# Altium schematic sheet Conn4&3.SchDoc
size A
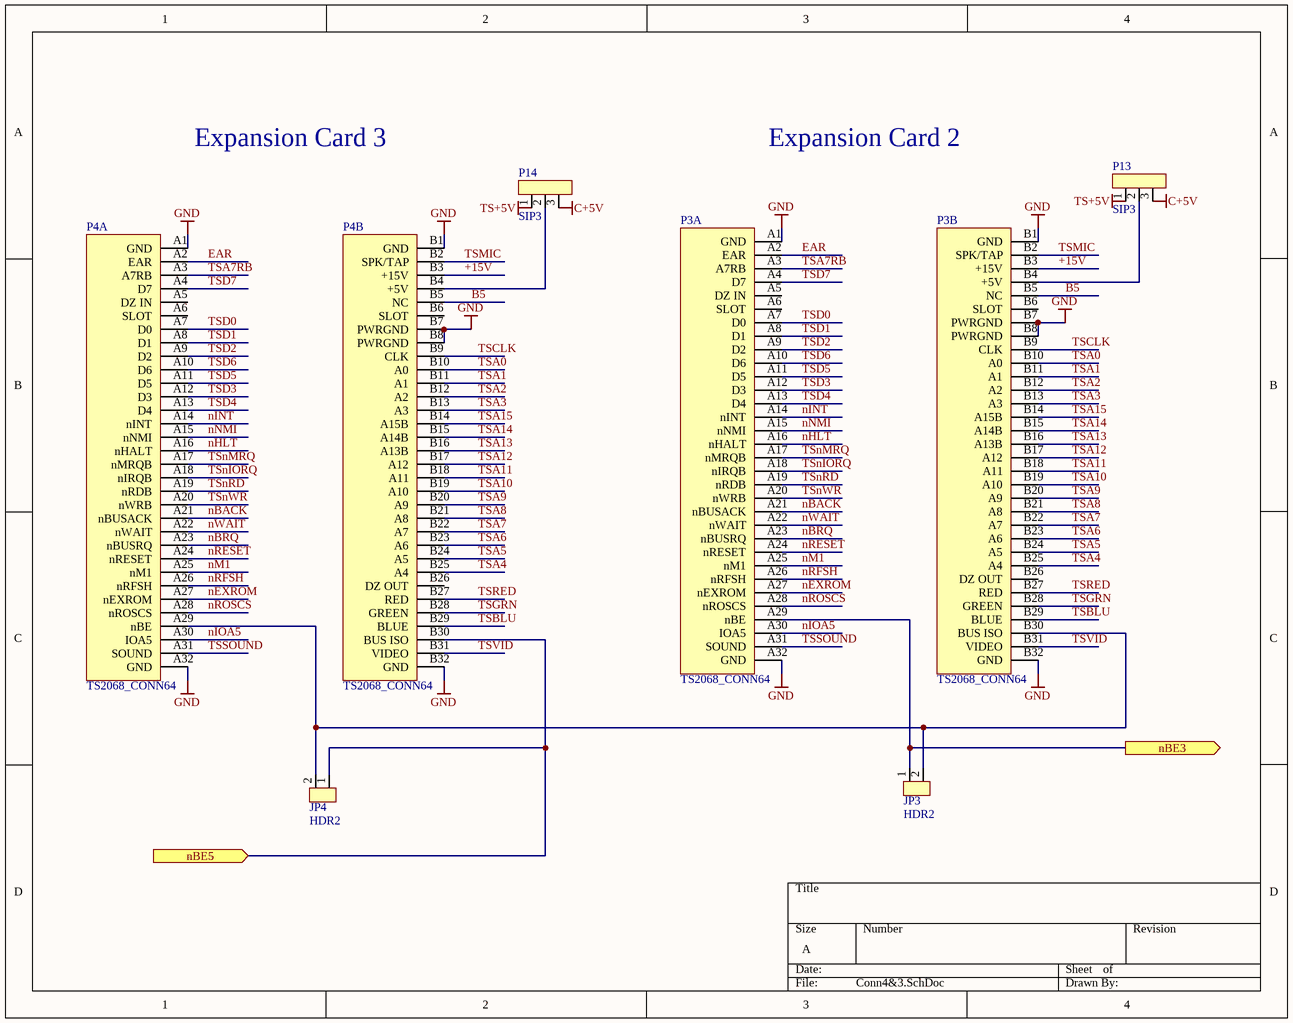
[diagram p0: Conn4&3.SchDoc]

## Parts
JP3  HDR2  [HDR2]
JP4  HDR2  [HDR2]
P3  TS2068_CONN64  [64CARDEDGE]  (parts A,B of 2)
P4  TS2068_CONN64  [64CARDEDGE]  (parts A,B of 2)
P13  SIP3  [SIP3]
P14  SIP3  [SIP3]

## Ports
nBE3 (out), nBE5 (in)

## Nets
C+5V: P13.3 P14.3
GND: P3.A1(GND) P3.A32(GND) P3.B1(GND) P3.B7(PWRGND) P3.B8(PWRGND) P3.B32(GND) P4.A1(GND) P4.A32(GND) P4.B1(GND) P4.B7(PWRGND) P4.B8(PWRGND) P4.B32(GND)
TS+5V: P13.1 P14.1
+15V: P3.B3(+15V) P4.B3(+15V)
B5: P3.B5(NC) P4.B5(NC)
EAR: P3.A2(EAR) P4.A2(EAR)
nBACK: P3.A21(nBUSACK) P4.A21(nBUSACK)
nBE3: JP3.1 P3.A29(nBE) ; port nBE3
nBE5: JP4.1 P4.B30(BUS_ISO) ; port nBE5
nBRQ: P3.A23(nBUSRQ) P4.A23(nBUSRQ)
nEXROM: P3.A27(nEXROM) P4.A27(nEXROM)
nHLT: P3.A16(nHALT) P4.A16(nHALT)
nINT: P3.A14(nINT) P4.A14(nINT)
nIOA5: P3.A30(IOA5) P4.A30(IOA5)
nM1: P3.A25(nM1) P4.A25(nM1)
nNMI: P3.A15(nNMI) P4.A15(nNMI)
nRESET: P3.A24(nRESET) P4.A24(nRESET)
nRFSH: P3.A26(nRFSH) P4.A26(nRFSH)
nROSCS: P3.A28(nROSCS) P4.A28(nROSCS)
nWAIT: P3.A22(nWAIT) P4.A22(nWAIT)
TSA0: P3.B10(A0) P4.B10(A0)
TSA1: P3.B11(A1) P4.B11(A1)
TSA2: P3.B12(A2) P4.B12(A2)
TSA3: P3.B13(A3) P4.B13(A3)
TSA4: P3.B25(A4) P4.B25(A4)
TSA5: P3.B24(A5) P4.B24(A5)
TSA6: P3.B23(A6) P4.B23(A6)
TSA7: P3.B22(A7) P4.B22(A7)
TSA7RB: P3.A3(A7RB) P4.A3(A7RB)
TSA8: P3.B21(A8) P4.B21(A8)
TSA9: P3.B20(A9) P4.B20(A9)
TSA10: P3.B19(A10) P4.B19(A10)
TSA11: P3.B18(A11) P4.B18(A11)
TSA12: P3.B17(A12) P4.B17(A12)
TSA13: P3.B16(A13B) P4.B16(A13B)
TSA14: P3.B15(A14B) P4.B15(A14B)
TSA15: P3.B14(A15B) P4.B14(A15B)
TSBLU: P3.B29(BLUE) P4.B29(BLUE)
TSCLK: P3.B9(CLK) P4.B9(CLK)
TSD0: P3.A7(D0) P4.A7(D0)
TSD1: P3.A8(D1) P4.A8(D1)
TSD2: P3.A9(D2) P4.A9(D2)
TSD3: P3.A12(D3) P4.A12(D3)
TSD4: P3.A13(D4) P4.A13(D4)
TSD5: P3.A11(D5) P4.A11(D5)
TSD6: P3.A10(D6) P4.A10(D6)
TSD7: P3.A4(D7) P4.A4(D7)
TSGRN: P3.B28(GREEN) P4.B28(GREEN)
TSMIC: P3.B2(SPK/TAP) P4.B2(SPK/TAP)
TSnIORQ: P3.A18(nIRQB) P4.A18(nIRQB)
TSnMRQ: P3.A17(nMRQB) P4.A17(nMRQB)
TSnRD: P3.A19(nRDB) P4.A19(nRDB)
TSnWR: P3.A20(nWRB) P4.A20(nWRB)
TSRED: P3.B27(RED) P4.B27(RED)
TSSOUND: P3.A31(SOUND) P4.A31(SOUND)
TSVID: P3.B31(VIDEO) P4.B31(VIDEO)
NetJP3_2: JP3.2 JP4.2 P3.B30(BUS_ISO) P4.A29(nBE)
NetP3_B4: P3.B4(+5V) P13.2
NetP4_B4: P4.B4(+5V) P14.2

Not connected (* = marked no-connect by the designer): P3 A5(DZ_IN) A6(SLOT) B6(SLOT) B26(DZ_OUT); P4 A5(DZ_IN) A6(SLOT) B6(SLOT) B26(DZ_OUT)

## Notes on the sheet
- Expansion Card 3
- Expansion Card 2

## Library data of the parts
P3 P4 = TS2068_CONN64: 64 Position Female Connector Non Specified - Dual Edge Gold 0.100" (2.54mm) Black; MFG: TD; MFG PN: 1761469-1; DK PN: 1761469-1-ND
